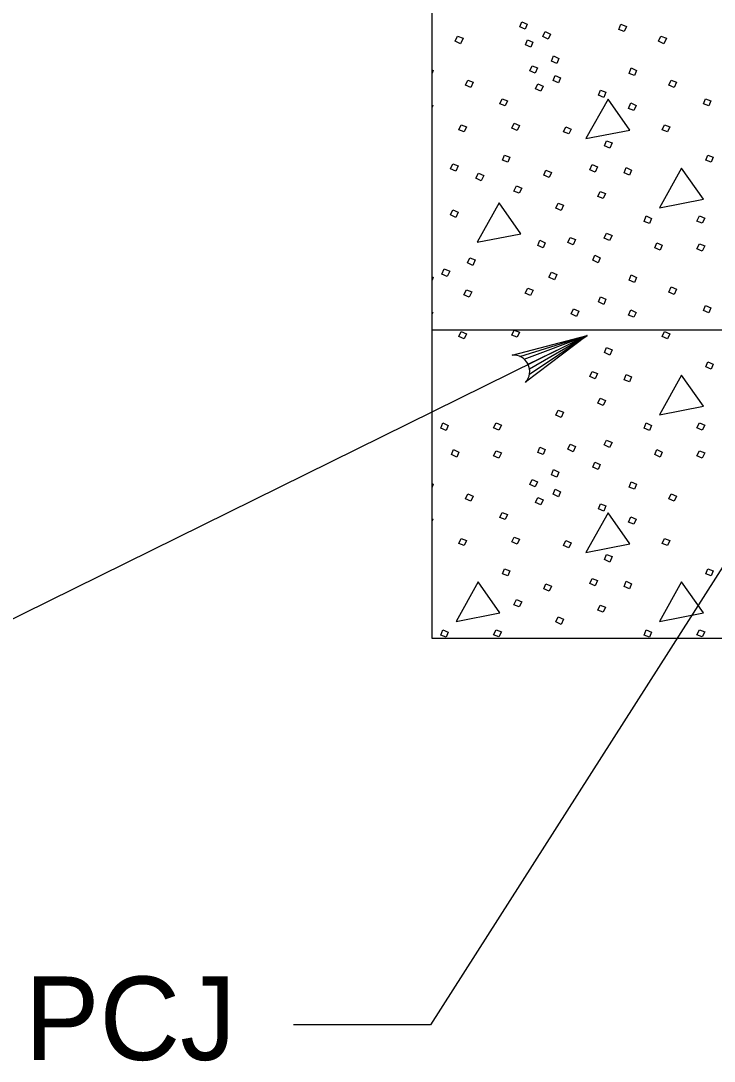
# Model space of a CAD drawing. Extents: x 0 to 34, y 0 to 22.
# Drawn here: x 8.046 to 9.341, y 1.385 to 3.328 of the extents above; entities that cross this region are included whole.
import ezdxf

# ---------------------------------------------------------------- set-up
doc = ezdxf.new("R2010")
doc.units = 0
doc.layers.add('Default', color=7, linetype='Continuous')

msp = doc.modelspace()

# ---------------------------------------------------------------- linework, layer by layer
at = {"layer": 'Default'}
for p, q in [((8.8136, 5.8753), (8.8136, 2.1752)), ((9.6392, 2.7511), (8.8114, 1.4527)), ((8.8136, 2.7511), (12.2445, 2.7511)), ((9.1037, 2.7403), (7.4133, 1.9058)), ((8.9784, 2.7015), (9.1037, 2.7403)), ((8.9864, 2.6962), (9.1037, 2.7403)), ((8.9935, 2.6868), (9.1037, 2.7403)), ((8.9962, 2.6781), (9.1037, 2.7403)), ((8.9962, 2.6682), (9.1037, 2.7403)), ((8.8136, 2.1752), (12.2445, 2.1752)), ((8.8114, 1.4527), (8.5555, 1.4527))]:
    msp.add_line(p, q, dxfattribs=at)
for points in [[(8.9819, 3.3262), (8.9919, 3.3222), (8.9879, 3.3129), (8.9779, 3.3169), (8.9819, 3.3262)], [(9.0252, 3.3082), (9.0352, 3.3036), (9.0312, 3.2942), (9.0212, 3.2989), (9.0252, 3.3082)], [(9.1671, 3.3222), (9.1771, 3.3176), (9.1731, 3.3082), (9.1631, 3.3122), (9.1671, 3.3222)], [(8.862, 3.2996), (8.872, 3.2956), (8.8673, 3.2856), (8.8573, 3.2902), (8.862, 3.2996)], [(8.9925, 3.2929), (9.0025, 3.2882), (8.9985, 3.2789), (8.9885, 3.2836), (8.9925, 3.2929)], [(9.2418, 3.2996), (9.2518, 3.2956), (9.2471, 3.2856), (9.2371, 3.2902), (9.2418, 3.2996)], [(9.041, 3.2628), (9.051, 3.2582), (9.047, 3.2488), (9.037, 3.2528), (9.041, 3.2628)], [(8.8136, 3.2368), (8.8164, 3.2355), (8.8136, 3.229)], [(9.001, 3.2442), (9.011, 3.2402), (9.007, 3.2308), (8.997, 3.2348), (9.001, 3.2442)], [(9.1862, 3.2402), (9.1962, 3.2355), (9.1922, 3.2262), (9.1822, 3.2302), (9.1862, 3.2402)], [(8.881, 3.2175), (8.891, 3.2135), (8.8864, 3.2035), (8.8764, 3.2082), (8.881, 3.2175)], [(9.0116, 3.2108), (9.0216, 3.2062), (9.0176, 3.1968), (9.0076, 3.2015), (9.0116, 3.2108)], [(9.0443, 3.2262), (9.0543, 3.2215), (9.0503, 3.2122), (9.0403, 3.2168), (9.0443, 3.2262)], [(9.2609, 3.2175), (9.2709, 3.2135), (9.2662, 3.2035), (9.2562, 3.2082), (9.2609, 3.2175)], [(9.129, 3.1988), (9.139, 3.1948), (9.135, 3.1848), (9.125, 3.1895), (9.129, 3.1988)], [(8.8136, 3.1712), (8.8157, 3.1702), (8.8136, 3.1659)], [(8.945, 3.1828), (8.955, 3.1788), (8.951, 3.1695), (8.941, 3.1735), (8.945, 3.1828)], [(9.143, 3.1822), (9.1016, 3.1082), (9.1835, 3.1242), (9.143, 3.1822)], [(9.1855, 3.1748), (9.1955, 3.1702), (9.1909, 3.1609), (9.1809, 3.1648), (9.1855, 3.1748)], [(9.3249, 3.1828), (9.3349, 3.1788), (9.3309, 3.1695), (9.3209, 3.1735), (9.3249, 3.1828)], [(8.8684, 3.1342), (8.8784, 3.1302), (8.8744, 3.1209), (8.8644, 3.1249), (8.8684, 3.1342)], [(8.9677, 3.1369), (8.9777, 3.1329), (8.973, 3.1236), (8.963, 3.1276), (8.9677, 3.1369)], [(9.0643, 3.1302), (9.0743, 3.1262), (9.0696, 3.1169), (9.0596, 3.1209), (9.0643, 3.1302)], [(9.2482, 3.1342), (9.2582, 3.1302), (9.2542, 3.1209), (9.2442, 3.1249), (9.2482, 3.1342)], [(9.1403, 3.1042), (9.1503, 3.1002), (9.1463, 3.0902), (9.1363, 3.0949), (9.1403, 3.1042)], [(8.9497, 3.0776), (8.9597, 3.0736), (8.9557, 3.0642), (8.9457, 3.0682), (8.9497, 3.0776)], [(9.3295, 3.0776), (9.3395, 3.0736), (9.3355, 3.0642), (9.3255, 3.0682), (9.3295, 3.0776)], [(8.853, 3.0613), (8.863, 3.0573), (8.8584, 3.0473), (8.8484, 3.052), (8.853, 3.0613)], [(9.113, 3.0596), (9.123, 3.0556), (9.119, 3.0456), (9.109, 3.0502), (9.113, 3.0596)], [(9.1769, 3.0542), (9.1869, 3.0496), (9.1829, 3.0402), (9.1729, 3.0442), (9.1769, 3.0542)], [(9.2802, 3.0529), (9.2389, 2.979), (9.3209, 2.995), (9.2802, 3.0529)], [(8.9007, 3.0435), (8.9107, 3.0395), (8.906, 3.0295), (8.896, 3.0342), (8.9007, 3.0435)], [(9.027, 3.0496), (9.037, 3.0449), (9.033, 3.0356), (9.023, 3.0402), (9.027, 3.0496)], [(8.9717, 3.0202), (8.9817, 3.0157), (8.977, 3.0063), (8.967, 3.0103), (8.9717, 3.0202)], [(9.1283, 3.0096), (9.1383, 3.0057), (9.1336, 2.9963), (9.1236, 3.0003), (9.1283, 3.0096)], [(8.853, 2.9749), (8.863, 2.9709), (8.8584, 2.9609), (8.8484, 2.9656), (8.853, 2.9749)], [(8.9395, 2.9885), (8.8983, 2.9145), (8.9802, 2.9305), (8.9395, 2.9885)], [(9.0496, 2.9877), (9.0596, 2.9837), (9.0556, 2.9737), (9.0456, 2.9783), (9.0496, 2.9877)], [(9.2142, 2.9637), (9.2242, 2.959), (9.2202, 2.9497), (9.2102, 2.9537), (9.2142, 2.9637)], [(9.3135, 2.9637), (9.3235, 2.9597), (9.3189, 2.9503), (9.3089, 2.9543), (9.3135, 2.9637)], [(9.0156, 2.9183), (9.0256, 2.9137), (9.0216, 2.9043), (9.0116, 2.9083), (9.0156, 2.9183)], [(9.0723, 2.9237), (9.0823, 2.9197), (9.0776, 2.9097), (9.0676, 2.9143), (9.0723, 2.9237)], [(9.1403, 2.9317), (9.1503, 2.927), (9.1456, 2.9177), (9.1356, 2.9223), (9.1403, 2.9317)], [(9.2342, 2.9137), (9.2442, 2.909), (9.2402, 2.8997), (9.2302, 2.9043), (9.2342, 2.9137)], [(9.3135, 2.9117), (9.3235, 2.9077), (9.3189, 2.8977), (9.3089, 2.9023), (9.3135, 2.9117)], [(8.8848, 2.8855), (8.8948, 2.8815), (8.8901, 2.8715), (8.8801, 2.8762), (8.8848, 2.8855)], [(9.1183, 2.8903), (9.1283, 2.8857), (9.1243, 2.8763), (9.1143, 2.881), (9.1183, 2.8903)], [(8.8371, 2.8647), (8.8471, 2.8607), (8.8425, 2.8507), (8.8325, 2.8553), (8.8371, 2.8647)], [(9.0373, 2.8587), (9.0473, 2.8547), (9.0426, 2.8447), (9.0326, 2.8493), (9.0373, 2.8587)], [(8.8136, 2.8504), (8.8164, 2.8491), (8.8136, 2.8425)], [(9.1862, 2.8537), (9.1962, 2.8491), (9.1922, 2.8397), (9.1822, 2.8437), (9.1862, 2.8537)], [(8.8785, 2.8259), (8.8885, 2.8219), (8.8838, 2.8119), (8.8738, 2.8166), (8.8785, 2.8259)], [(8.9928, 2.8289), (9.0028, 2.8249), (8.9981, 2.8149), (8.9882, 2.8196), (8.9928, 2.8289)], [(9.2609, 2.8311), (9.2709, 2.8271), (9.2662, 2.8171), (9.2562, 2.8217), (9.2609, 2.8311)], [(9.129, 2.8124), (9.139, 2.8084), (9.135, 2.7984), (9.125, 2.8031), (9.129, 2.8124)], [(8.8136, 2.7847), (8.8157, 2.7837), (8.8136, 2.7795)], [(9.0786, 2.7902), (9.0886, 2.7862), (9.084, 2.7762), (9.074, 2.7808), (9.0786, 2.7902)], [(9.1855, 2.7884), (9.1955, 2.7837), (9.1909, 2.7744), (9.1809, 2.7784), (9.1855, 2.7884)], [(9.3249, 2.7964), (9.3349, 2.7924), (9.3309, 2.7831), (9.3209, 2.7871), (9.3249, 2.7964)], [(8.8684, 2.7477), (8.8784, 2.7437), (8.8744, 2.7344), (8.8644, 2.7384), (8.8684, 2.7477)], [(8.9677, 2.7504), (8.9777, 2.7464), (8.973, 2.7371), (8.963, 2.7411), (8.9677, 2.7504)], [(9.2482, 2.7477), (9.2582, 2.7437), (9.2542, 2.7344), (9.2442, 2.7384), (9.2482, 2.7477)], [(8.964, 2.7039), (9.1037, 2.7403), (8.9887, 2.653)], [(9.1403, 2.7178), (9.1503, 2.7138), (9.1463, 2.7038), (9.1363, 2.7085), (9.1403, 2.7178)], [(9.3295, 2.6912), (9.3395, 2.6872), (9.3355, 2.6778), (9.3255, 2.6818), (9.3295, 2.6912)], [(9.113, 2.6732), (9.123, 2.6692), (9.119, 2.6592), (9.109, 2.6638), (9.113, 2.6732)], [(9.1769, 2.6678), (9.1869, 2.6632), (9.1829, 2.6538), (9.1729, 2.6578), (9.1769, 2.6678)], [(9.2802, 2.6665), (9.2389, 2.5925), (9.3209, 2.6085), (9.2802, 2.6665)], [(9.1283, 2.6232), (9.1383, 2.6192), (9.1336, 2.6098), (9.1236, 2.6138), (9.1283, 2.6232)], [(9.0496, 2.6012), (9.0596, 2.5972), (9.0556, 2.5872), (9.0456, 2.5918), (9.0496, 2.6012)], [(8.8344, 2.5772), (8.8444, 2.5726), (8.8404, 2.5632), (8.8304, 2.5672), (8.8344, 2.5772)], [(8.9337, 2.5772), (8.9437, 2.5732), (8.939, 2.5639), (8.929, 2.5679), (8.9337, 2.5772)], [(9.2142, 2.5772), (9.2242, 2.5726), (9.2202, 2.5632), (9.2102, 2.5672), (9.2142, 2.5772)], [(9.3135, 2.5772), (9.3235, 2.5732), (9.3189, 2.5639), (9.3089, 2.5679), (9.3135, 2.5772)], [(8.8544, 2.5272), (8.8644, 2.5226), (8.8604, 2.5132), (8.8504, 2.5179), (8.8544, 2.5272)], [(9.0156, 2.5319), (9.0256, 2.5272), (9.0216, 2.5179), (9.0116, 2.5219), (9.0156, 2.5319)], [(9.0723, 2.5372), (9.0823, 2.5332), (9.0776, 2.5232), (9.0676, 2.5279), (9.0723, 2.5372)], [(9.1403, 2.5452), (9.1503, 2.5406), (9.1456, 2.5312), (9.1356, 2.5359), (9.1403, 2.5452)], [(9.2342, 2.5272), (9.2442, 2.5226), (9.2402, 2.5132), (9.2302, 2.5179), (9.2342, 2.5272)], [(8.9337, 2.5252), (8.9437, 2.5212), (8.939, 2.5112), (8.929, 2.5159), (8.9337, 2.5252)], [(9.3135, 2.5252), (9.3235, 2.5212), (9.3189, 2.5112), (9.3089, 2.5159), (9.3135, 2.5252)], [(9.041, 2.4899), (9.051, 2.4852), (9.047, 2.4759), (9.037, 2.4799), (9.041, 2.4899)], [(9.1183, 2.5039), (9.1283, 2.4992), (9.1243, 2.4899), (9.1143, 2.4946), (9.1183, 2.5039)], [(9.001, 2.4712), (9.011, 2.4672), (9.007, 2.4579), (8.997, 2.4619), (9.001, 2.4712)], [(8.8136, 2.4639), (8.8164, 2.4626), (8.8136, 2.4561)], [(9.0443, 2.4532), (9.0543, 2.4486), (9.0503, 2.4392), (9.0403, 2.4439), (9.0443, 2.4532)], [(9.1862, 2.4672), (9.1962, 2.4626), (9.1922, 2.4532), (9.1822, 2.4572), (9.1862, 2.4672)], [(8.881, 2.4446), (8.891, 2.4406), (8.8864, 2.4307), (8.8764, 2.4352), (8.881, 2.4446)], [(9.0116, 2.4379), (9.0216, 2.4332), (9.0176, 2.424), (9.0076, 2.4287), (9.0116, 2.4379)], [(9.2609, 2.4446), (9.2709, 2.4406), (9.2662, 2.4307), (9.2562, 2.4352), (9.2609, 2.4446)], [(9.129, 2.426), (9.139, 2.422), (9.135, 2.412), (9.125, 2.4167), (9.129, 2.426)], [(8.8136, 2.3983), (8.8157, 2.3973), (8.8136, 2.3931)], [(8.945, 2.41), (8.955, 2.406), (8.951, 2.3967), (8.941, 2.4007), (8.945, 2.41)], [(9.143, 2.4093), (9.1016, 2.3353), (9.1835, 2.3513), (9.143, 2.4093)], [(9.1855, 2.402), (9.1955, 2.3973), (9.1909, 2.388), (9.1809, 2.392), (9.1855, 2.402)], [(8.8684, 2.3613), (8.8784, 2.3573), (8.8744, 2.348), (8.8644, 2.352), (8.8684, 2.3613)], [(8.9677, 2.364), (8.9777, 2.36), (8.973, 2.3507), (8.963, 2.3547), (8.9677, 2.364)], [(9.0643, 2.3573), (9.0743, 2.3533), (9.0696, 2.344), (9.0596, 2.348), (9.0643, 2.3573)], [(9.2482, 2.3613), (9.2582, 2.3573), (9.2542, 2.348), (9.2442, 2.352), (9.2482, 2.3613)], [(9.1403, 2.3313), (9.1503, 2.3273), (9.1463, 2.3173), (9.1363, 2.322), (9.1403, 2.3313)], [(8.9497, 2.3047), (8.9597, 2.3007), (8.9557, 2.2913), (8.9457, 2.2953), (8.9497, 2.3047)], [(9.3295, 2.3047), (9.3395, 2.3007), (9.3355, 2.2913), (9.3255, 2.2953), (9.3295, 2.3047)], [(8.9004, 2.2801), (8.859, 2.2061), (8.941, 2.2221), (8.9004, 2.2801)], [(9.027, 2.2767), (9.037, 2.2721), (9.033, 2.2627), (9.023, 2.2674), (9.027, 2.2767)], [(9.113, 2.2867), (9.123, 2.2827), (9.119, 2.2727), (9.109, 2.2774), (9.113, 2.2867)], [(9.1769, 2.2814), (9.1869, 2.2767), (9.1829, 2.2674), (9.1729, 2.2714), (9.1769, 2.2814)], [(9.2802, 2.2801), (9.2389, 2.2061), (9.3209, 2.2221), (9.2802, 2.2801)], [(8.9717, 2.2474), (8.9817, 2.2427), (8.977, 2.2334), (8.967, 2.2374), (8.9717, 2.2474)], [(9.1283, 2.2367), (9.1383, 2.2327), (9.1336, 2.2234), (9.1236, 2.2274), (9.1283, 2.2367)], [(9.0496, 2.2147), (9.0596, 2.2107), (9.0556, 2.2007), (9.0456, 2.2054), (9.0496, 2.2147)], [(8.8344, 2.1907), (8.8444, 2.1861), (8.8404, 2.1767), (8.8304, 2.1807), (8.8344, 2.1907)], [(8.9337, 2.1907), (8.9437, 2.1867), (8.939, 2.1774), (8.929, 2.1814), (8.9337, 2.1907)], [(9.2142, 2.1907), (9.2242, 2.1861), (9.2202, 2.1767), (9.2102, 2.1807), (9.2142, 2.1907)], [(9.3135, 2.1907), (9.3235, 2.1867), (9.3189, 2.1774), (9.3089, 2.1814), (9.3135, 2.1907)]]:
    msp.add_lwpolyline(points, dxfattribs=at)
msp.add_arc((8.966, 2.6734), 0.0306, 317.9861, 93.8122, dxfattribs=at)

# ---------------------------------------------------------------- texts
msp.add_text('PCJ', height=0.156, dxfattribs=at).set_placement((8.0539, 1.387))

doc.saveas('drawing.dxf')
